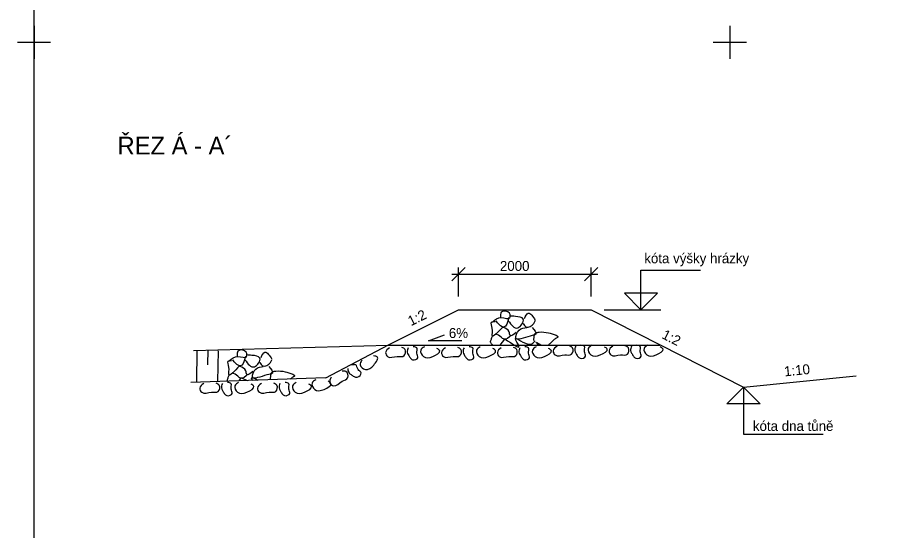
# Model space of a CAD drawing. Extents: x -463095.2 to -463015.6, y -1105044.4 to -1104976.7.
# Drawn here: x -463058.63 to -463032.2, y -1105021.66 to -1105006.18 of the extents above; entities that cross this region are included whole.
import ezdxf

# ---------------------------------------------------------------- set-up
doc = ezdxf.new("R2010")
doc.units = 0
for name, color, linetype in [('Implicitní', 7, 'Continuous'), ('KOTA', 7, 'Continuous'), ('KOTA_DELKY', 7, 'Continuous'), ('NS_V_PF', 7, 'Continuous'), ('REZY_PF_PUVODNI', 7, 'Continuous'), ('SKLON', 7, 'Continuous'), ('Vrstva 14', 7, 'Continuous')]:
    doc.layers.add(name, color=color, linetype=linetype)

msp = doc.modelspace()

# ---------------------------------------------------------------- linework, layer by layer
at = {"layer": 'Implicitní'}
for p, q in [((-463058.132, -1105006.432), (-463058.132, -1105007.432)), ((-463058.132, -1105006.432), (-463058.132, -1105007.432)), ((-463058.132, -1105006.432), (-463058.132, -1105007.432)), ((-463058.132, -1105006.432), (-463058.132, -1105007.432)), ((-463058.132, -1105006.432), (-463058.132, -1105007.432)), ((-463058.132, -1105006.432), (-463058.132, -1105007.432)), ((-463058.132, -1105006.432), (-463058.132, -1105007.432)), ((-463058.132, -1105006.432), (-463058.132, -1105007.432)), ((-463058.132, -1105006.432), (-463058.132, -1105007.432)), ((-463058.132, -1105006.432), (-463058.132, -1105007.432)), ((-463058.132, -1105006.432), (-463058.132, -1105007.432)), ((-463058.132, -1105006.432), (-463058.132, -1105007.432)), ((-463058.132, -1105006.432), (-463058.132, -1105007.432)), ((-463058.132, -1105006.432), (-463058.132, -1105007.432)), ((-463058.132, -1105006.432), (-463058.132, -1105007.432)), ((-463058.132, -1105006.432), (-463058.132, -1105007.432)), ((-463058.132, -1105006.432), (-463058.132, -1105007.432)), ((-463058.132, -1105006.432), (-463058.132, -1105007.432)), ((-463058.132, -1105006.432), (-463058.132, -1105007.432)), ((-463058.132, -1105006.432), (-463058.132, -1105007.432)), ((-463058.132, -1105006.432), (-463058.132, -1105007.432)), ((-463058.132, -1105006.432), (-463058.132, -1105007.432)), ((-463058.132, -1105006.432), (-463058.132, -1105007.432)), ((-463058.132, -1105006.432), (-463058.132, -1105007.432)), ((-463058.132, -1105006.432), (-463058.132, -1105007.432)), ((-463058.132, -1105006.432), (-463058.132, -1105007.432)), ((-463058.132, -1105006.432), (-463058.132, -1105007.432)), ((-463058.132, -1105006.432), (-463058.132, -1105007.432)), ((-463037.132, -1105006.432), (-463037.132, -1105007.432)), ((-463037.132, -1105006.432), (-463037.132, -1105007.432)), ((-463037.132, -1105006.432), (-463037.132, -1105007.432)), ((-463037.132, -1105006.432), (-463037.132, -1105007.432)), ((-463037.132, -1105006.432), (-463037.132, -1105007.432)), ((-463037.132, -1105006.432), (-463037.132, -1105007.432)), ((-463037.132, -1105006.432), (-463037.132, -1105007.432)), ((-463037.132, -1105006.432), (-463037.132, -1105007.432)), ((-463037.132, -1105006.432), (-463037.132, -1105007.432)), ((-463037.132, -1105006.432), (-463037.132, -1105007.432)), ((-463037.132, -1105006.432), (-463037.132, -1105007.432)), ((-463037.132, -1105006.432), (-463037.132, -1105007.432)), ((-463037.132, -1105006.432), (-463037.132, -1105007.432)), ((-463037.132, -1105006.432), (-463037.132, -1105007.432)), ((-463037.132, -1105006.432), (-463037.132, -1105007.432)), ((-463037.132, -1105006.432), (-463037.132, -1105007.432)), ((-463037.132, -1105006.432), (-463037.132, -1105007.432)), ((-463037.132, -1105006.432), (-463037.132, -1105007.432)), ((-463037.132, -1105006.432), (-463037.132, -1105007.432)), ((-463037.132, -1105006.432), (-463037.132, -1105007.432)), ((-463037.132, -1105006.432), (-463037.132, -1105007.432)), ((-463037.132, -1105006.432), (-463037.132, -1105007.432)), ((-463037.132, -1105006.432), (-463037.132, -1105007.432)), ((-463037.132, -1105006.432), (-463037.132, -1105007.432)), ((-463037.132, -1105006.432), (-463037.132, -1105007.432)), ((-463037.132, -1105006.432), (-463037.132, -1105007.432)), ((-463037.132, -1105006.432), (-463037.132, -1105007.432)), ((-463037.132, -1105006.432), (-463037.132, -1105007.432)), ((-463037.132, -1105006.432), (-463037.132, -1105007.432)), ((-463037.132, -1105006.432), (-463037.132, -1105007.432)), ((-463037.132, -1105006.432), (-463037.132, -1105007.432)), ((-463037.132, -1105006.432), (-463037.132, -1105007.432)), ((-463037.132, -1105006.432), (-463037.132, -1105007.432)), ((-463037.132, -1105006.432), (-463037.132, -1105007.432)), ((-463037.132, -1105006.432), (-463037.132, -1105007.432)), ((-463037.132, -1105006.432), (-463037.132, -1105007.432)), ((-463037.132, -1105006.432), (-463037.132, -1105007.432)), ((-463037.132, -1105006.432), (-463037.132, -1105007.432)), ((-463037.132, -1105006.432), (-463037.132, -1105007.432)), ((-463037.132, -1105006.432), (-463037.132, -1105007.432)), ((-463037.132, -1105006.432), (-463037.132, -1105007.432)), ((-463037.132, -1105006.432), (-463037.132, -1105007.432)), ((-463057.632, -1105006.932), (-463058.632, -1105006.932)), ((-463057.632, -1105006.932), (-463058.632, -1105006.932)), ((-463057.632, -1105006.932), (-463058.632, -1105006.932)), ((-463057.632, -1105006.932), (-463058.632, -1105006.932)), ((-463057.632, -1105006.932), (-463058.632, -1105006.932)), ((-463057.632, -1105006.932), (-463058.632, -1105006.932)), ((-463036.632, -1105006.932), (-463037.632, -1105006.932)), ((-463036.632, -1105006.932), (-463037.632, -1105006.932)), ((-463036.632, -1105006.932), (-463037.632, -1105006.932)), ((-463036.632, -1105006.932), (-463037.632, -1105006.932)), ((-463036.632, -1105006.932), (-463037.632, -1105006.932)), ((-463036.632, -1105006.932), (-463037.632, -1105006.932)), ((-463036.632, -1105006.932), (-463037.632, -1105006.932)), ((-463036.632, -1105006.932), (-463037.632, -1105006.932)), ((-463036.632, -1105006.932), (-463037.632, -1105006.932)), ((-463036.632, -1105006.932), (-463037.632, -1105006.932))]:
    msp.add_line(p, q, dxfattribs=at)
msp.add_lwpolyline([(-463058.132, -1104977.232), (-463016.132, -1104977.232), (-463016.132, -1105036.632), (-463058.132, -1105036.632)], close=True, dxfattribs=at)
at = {"layer": 'KOTA'}
for points in [[(-463039.817, -1105014.5), (-463040.317, -1105014.5), (-463039.817, -1105015), (-463039.817, -1105013.8), (-463038.017, -1105013.8)], [(-463039.817, -1105015), (-463039.317, -1105014.5), (-463039.817, -1105014.5)], [(-463043.319, -1105015), (-463041.326, -1105015)], [(-463040.924, -1105015), (-463039.817, -1105015), (-463039.217, -1105015)], [(-463036.723, -1105017.835), (-463037.223, -1105017.835), (-463036.723, -1105017.335), (-463036.723, -1105018.754), (-463034.322, -1105018.754)], [(-463036.723, -1105017.335), (-463036.223, -1105017.835), (-463036.723, -1105017.835)]]:
    msp.add_lwpolyline(points, dxfattribs=at)
at = {"layer": 'KOTA_DELKY'}
for points in [[(-463045.519, -1105014.127), (-463045.119, -1105013.727)], [(-463045.319, -1105014.6), (-463045.319, -1105013.727)], [(-463041.519, -1105014.127), (-463041.119, -1105013.727)], [(-463041.319, -1105014.6), (-463041.319, -1105013.727)], [(-463045.519, -1105013.927), (-463041.119, -1105013.927)]]:
    msp.add_lwpolyline(points, dxfattribs=at)
at = {"layer": 'NS_V_PF'}
for points in [[(-463047.452, -1105016.067), (-463045.319, -1105015), (-463043.319, -1105015), (-463041.319, -1105015), (-463039.238, -1105016.058)], [(-463039.238, -1105016.058), (-463036.723, -1105017.335), (-463033.319, -1105016.994)]]:
    msp.add_lwpolyline(points, dxfattribs=at)
at = {"layer": 'REZY_PF_PUVODNI'}
msp.add_lwpolyline([(-463053.319, -1105016.225), (-463047.443, -1105016.066)], dxfattribs=at)
at = {"layer": 'Vrstva 14'}
for p, q in [((-463047.443, -1105016.066), (-463049.34, -1105017.058)), ((-463047.443, -1105016.066), (-463039.242, -1105016.066)), ((-463043.939, -1105015.881), (-463044.073, -1105016.066)), ((-463042.993, -1105015.979), (-463042.906, -1105016.066)), ((-463042.835, -1105016.066), (-463042.955, -1105015.999)), ((-463053.224, -1105017.189), (-463053.21, -1105016.215)), ((-463052.886, -1105016.659), (-463052.88, -1105016.207)), ((-463052.581, -1105017.167), (-463052.568, -1105016.233)), ((-463049.334, -1105017.054), (-463053.398, -1105017.195)), ((-463051.887, -1105017.056), (-463051.951, -1105017.145)), ((-463051.873, -1105017.05), (-463051.7, -1105017.136)), ((-463050.957, -1105017.111), (-463050.953, -1105017.108))]:
    msp.add_line(p, q, dxfattribs=at)
msp.add_lwpolyline([(-463045.224, -1105015.94), (-463046.227, -1105015.94), (-463045.741, -1105015.752)], dxfattribs=at)
for points in [[(-463044.291, -1105015.365), (-463044.031, -1105015.235), (-463043.771, -1105015.235), (-463043.783, -1105015.105), (-463044.031, -1105015.069), (-463044.055, -1105015.223)], [(-463043.807, -1105015.235), (-463043.961, -1105015.519), (-463044.149, -1105015.389), (-463044.185, -1105015.329)], [(-463043.819, -1105015.329), (-463043.535, -1105015.543), (-463043.371, -1105015.283), (-463043.607, -1105015.199), (-463043.761, -1105015.187)], [(-463043.371, -1105015.413), (-463043.277, -1105015.519), (-463043.053, -1105015.413), (-463043.005, -1105015.329)], [(-463043.335, -1105015.259), (-463043.217, -1105015.105), (-463043.005, -1105015.317)], [(-463043.985, -1105015.519), (-463044.303, -1105015.779), (-463044.303, -1105015.555), (-463044.327, -1105015.377), (-463044.221, -1105015.353)], [(-463043.583, -1105015.685), (-463043.761, -1105015.779), (-463043.795, -1105015.661), (-463043.961, -1105015.531)], [(-463043.099, -1105015.531), (-463042.993, -1105015.733), (-463043.159, -1105015.791), (-463043.595, -1105015.851), (-463043.489, -1105015.613), (-463043.265, -1105015.531)], [(-463044.288, -1105016.066), (-463044.291, -1105016.063), (-463044.305, -1105016.049), (-463044.34, -1105016.006), (-463044.353, -1105015.976), (-463044.354, -1105015.96), (-463044.353, -1105015.953), (-463044.351, -1105015.945), (-463044.337, -1105015.902), (-463044.323, -1105015.86), (-463044.308, -1105015.817), (-463044.293, -1105015.775)], [(-463043.729, -1105015.763), (-463043.949, -1105015.887), (-463044.031, -1105015.827), (-463044.209, -1105015.721)], [(-463043.925, -1105015.875), (-463043.501, -1105016.087), (-463043.607, -1105015.875), (-463043.159, -1105016.039), (-463043.005, -1105015.933)], [(-463043.053, -1105015.921), (-463043.049, -1105015.882), (-463043.044, -1105015.843), (-463043.039, -1105015.804), (-463043.033, -1105015.765), (-463043.031, -1105015.755), (-463043.028, -1105015.745), (-463043.019, -1105015.728), (-463042.988, -1105015.7), (-463042.887, -1105015.671), (-463042.61, -1105015.692), (-463042.373, -1105015.768), (-463042.325, -1105015.809), (-463042.327, -1105015.827), (-463042.337, -1105015.836), (-463042.343, -1105015.839), (-463042.347, -1105015.841), (-463042.349, -1105015.842), (-463042.351, -1105015.843), (-463042.368, -1105015.85), (-463042.417, -1105015.883), (-463042.483, -1105015.942), (-463042.55, -1105016.008), (-463042.584, -1105016.039), (-463042.618, -1105016.066)], [(-463046.841, -1105016.143), (-463046.87, -1105016.278), (-463046.839, -1105016.352), (-463046.784, -1105016.441), (-463046.707, -1105016.508), (-463046.547, -1105016.444), (-463046.579, -1105016.311), (-463046.579, -1105016.15), (-463046.688, -1105016.113)], [(-463046.35, -1105016.113), (-463046.462, -1105016.215), (-463046.383, -1105016.407), (-463046.1, -1105016.407), (-463045.891, -1105016.231), (-463045.975, -1105016.162)], [(-463045.156, -1105016.143), (-463045.185, -1105016.278), (-463045.154, -1105016.352), (-463045.099, -1105016.441), (-463045.022, -1105016.508), (-463044.861, -1105016.444), (-463044.893, -1105016.311), (-463044.893, -1105016.15), (-463045.003, -1105016.113)], [(-463044.664, -1105016.113), (-463044.776, -1105016.215), (-463044.697, -1105016.407), (-463044.415, -1105016.407), (-463044.206, -1105016.231), (-463044.29, -1105016.162)], [(-463043.47, -1105016.143), (-463043.499, -1105016.278), (-463043.469, -1105016.352), (-463043.413, -1105016.441), (-463043.336, -1105016.508), (-463043.176, -1105016.444), (-463043.208, -1105016.311), (-463043.208, -1105016.15), (-463043.317, -1105016.113)], [(-463042.979, -1105016.113), (-463043.091, -1105016.215), (-463043.012, -1105016.407), (-463042.729, -1105016.407), (-463042.52, -1105016.231), (-463042.604, -1105016.162)], [(-463042.348, -1105016.096), (-463042.466, -1105016.239), (-463042.407, -1105016.362), (-463042.117, -1105016.362), (-463041.91, -1105016.336), (-463041.88, -1105016.15), (-463041.976, -1105016.089)], [(-463041.786, -1105016.096), (-463041.814, -1105016.232), (-463041.784, -1105016.306), (-463041.728, -1105016.395), (-463041.651, -1105016.462), (-463041.491, -1105016.398), (-463041.523, -1105016.265), (-463041.523, -1105016.103), (-463041.632, -1105016.067)], [(-463041.294, -1105016.067), (-463041.406, -1105016.169), (-463041.327, -1105016.36), (-463041.044, -1105016.36), (-463040.835, -1105016.184), (-463040.92, -1105016.115)], [(-463040.663, -1105016.096), (-463040.78, -1105016.239), (-463040.722, -1105016.362), (-463040.431, -1105016.362), (-463040.225, -1105016.336), (-463040.194, -1105016.15), (-463040.291, -1105016.089)], [(-463040.1, -1105016.096), (-463040.129, -1105016.232), (-463040.098, -1105016.306), (-463040.043, -1105016.395), (-463039.966, -1105016.462), (-463039.806, -1105016.398), (-463039.838, -1105016.265), (-463039.838, -1105016.103), (-463039.947, -1105016.067)], [(-463039.609, -1105016.067), (-463039.721, -1105016.169), (-463039.642, -1105016.36), (-463039.359, -1105016.36), (-463039.15, -1105016.184), (-463039.234, -1105016.115)], [(-463052.239, -1105016.54), (-463051.979, -1105016.41), (-463051.719, -1105016.41), (-463051.731, -1105016.28), (-463051.979, -1105016.244), (-463052.003, -1105016.398)], [(-463051.767, -1105016.504), (-463051.483, -1105016.718), (-463051.319, -1105016.458), (-463051.555, -1105016.374), (-463051.709, -1105016.362)], [(-463051.283, -1105016.434), (-463051.165, -1105016.28), (-463050.953, -1105016.492)], [(-463047.404, -1105016.143), (-463047.521, -1105016.286), (-463047.463, -1105016.408), (-463047.172, -1105016.408), (-463046.966, -1105016.382), (-463046.935, -1105016.196), (-463047.032, -1105016.135)], [(-463045.719, -1105016.143), (-463045.836, -1105016.286), (-463045.777, -1105016.408), (-463045.487, -1105016.408), (-463045.28, -1105016.382), (-463045.25, -1105016.196), (-463045.347, -1105016.135)], [(-463044.033, -1105016.143), (-463044.15, -1105016.286), (-463044.092, -1105016.408), (-463043.801, -1105016.408), (-463043.595, -1105016.382), (-463043.564, -1105016.196), (-463043.661, -1105016.135)], [(-463051.933, -1105016.694), (-463052.251, -1105016.954), (-463052.251, -1105016.73), (-463052.275, -1105016.552), (-463052.169, -1105016.528)], [(-463051.755, -1105016.41), (-463051.909, -1105016.694), (-463052.097, -1105016.564), (-463052.133, -1105016.504)], [(-463051.319, -1105016.588), (-463051.225, -1105016.694), (-463051.001, -1105016.588), (-463050.953, -1105016.504)], [(-463048.662, -1105016.77), (-463048.626, -1105016.904), (-463048.565, -1105016.956), (-463048.475, -1105017.01), (-463048.376, -1105017.034), (-463048.262, -1105016.904), (-463048.352, -1105016.801), (-463048.425, -1105016.657), (-463048.539, -1105016.674)], [(-463048.238, -1105016.52), (-463048.291, -1105016.662), (-463048.134, -1105016.796), (-463047.882, -1105016.667), (-463047.777, -1105016.415), (-463047.883, -1105016.392)], [(-463051.677, -1105016.938), (-463051.897, -1105017.062), (-463051.979, -1105017.002), (-463052.157, -1105016.896)], [(-463051.531, -1105016.86), (-463051.709, -1105016.954), (-463051.743, -1105016.836), (-463051.909, -1105016.706)], [(-463051.047, -1105016.706), (-463050.941, -1105016.908), (-463051.107, -1105016.966), (-463051.543, -1105017.026), (-463051.437, -1105016.788), (-463051.213, -1105016.706)], [(-463051.001, -1105017.096), (-463050.996, -1105017.057), (-463050.991, -1105017.018), (-463050.986, -1105016.979), (-463050.981, -1105016.94), (-463050.979, -1105016.93), (-463050.976, -1105016.92), (-463050.966, -1105016.903), (-463050.935, -1105016.875), (-463050.835, -1105016.846), (-463050.557, -1105016.867), (-463050.321, -1105016.943), (-463050.272, -1105016.984), (-463050.275, -1105017.002), (-463050.284, -1105017.011), (-463050.291, -1105017.014), (-463050.294, -1105017.016), (-463050.299, -1105017.018), (-463050.305, -1105017.021), (-463050.312, -1105017.024), (-463050.325, -1105017.031), (-463050.351, -1105017.048), (-463050.377, -1105017.068), (-463050.404, -1105017.091)], [(-463049.163, -1105017.027), (-463049.202, -1105017.208), (-463049.094, -1105017.29), (-463048.835, -1105017.157), (-463048.663, -1105017.04), (-463048.721, -1105016.861), (-463048.835, -1105016.851)], [(-463052.298, -1105017.157), (-463052.302, -1105017.139), (-463052.299, -1105017.12), (-463052.285, -1105017.077), (-463052.27, -1105017.035), (-463052.255, -1105016.993), (-463052.241, -1105016.95)], [(-463051.532, -1105017.131), (-463051.542, -1105017.116), (-463051.551, -1105017.101), (-463051.555, -1105017.095), (-463051.558, -1105017.089), (-463051.561, -1105017.083), (-463051.563, -1105017.077), (-463051.565, -1105017.072), (-463051.566, -1105017.068), (-463051.566, -1105017.063), (-463051.566, -1105017.059), (-463051.562, -1105017.053), (-463051.555, -1105017.05), (-463051.529, -1105017.049), (-463051.503, -1105017.054), (-463051.489, -1105017.058), (-463051.474, -1105017.064), (-463051.454, -1105017.074), (-463051.448, -1105017.078), (-463051.412, -1105017.101), (-463051.377, -1105017.125)], [(-463049.63, -1105017.107), (-463049.742, -1105017.209), (-463049.663, -1105017.4), (-463049.38, -1105017.4), (-463049.171, -1105017.224), (-463049.255, -1105017.156)], [(-463053.012, -1105017.221), (-463053.13, -1105017.364), (-463053.071, -1105017.486), (-463052.781, -1105017.486), (-463052.574, -1105017.461), (-463052.544, -1105017.275), (-463052.64, -1105017.214)], [(-463052.45, -1105017.221), (-463052.478, -1105017.356), (-463052.448, -1105017.431), (-463052.393, -1105017.52), (-463052.315, -1105017.587), (-463052.155, -1105017.522), (-463052.187, -1105017.39), (-463052.187, -1105017.228), (-463052.296, -1105017.192)], [(-463051.958, -1105017.192), (-463052.07, -1105017.294), (-463051.991, -1105017.485), (-463051.708, -1105017.485), (-463051.5, -1105017.309), (-463051.584, -1105017.24)], [(-463051.272, -1105017.221), (-463051.39, -1105017.364), (-463051.331, -1105017.486), (-463051.041, -1105017.486), (-463050.834, -1105017.461), (-463050.804, -1105017.275), (-463050.9, -1105017.214)], [(-463050.71, -1105017.221), (-463050.738, -1105017.356), (-463050.708, -1105017.431), (-463050.652, -1105017.52), (-463050.575, -1105017.587), (-463050.415, -1105017.522), (-463050.447, -1105017.39), (-463050.447, -1105017.228), (-463050.556, -1105017.192)], [(-463050.218, -1105017.192), (-463050.33, -1105017.294), (-463050.251, -1105017.485), (-463049.968, -1105017.485), (-463049.76, -1105017.309), (-463049.844, -1105017.24)]]:
    msp.add_spline(points, degree=3, dxfattribs=at)

# ---------------------------------------------------------------- texts
at = {"layer": 'KOTA'}
for s, p in [('kóta výšky hrázky', (-463039.716, -1105013.595)), ('kóta dna tůně', (-463036.438, -1105018.654))]:
    msp.add_text(s, height=0.3, dxfattribs=at).set_placement(p)
at = {"layer": 'KOTA_DELKY'}
for s, p in [('2000', (-463044.073, -1105013.827)), ('6%', (-463045.614, -1105015.85))]:
    msp.add_text(s, height=0.3, dxfattribs=at).set_placement(p)
at = {"layer": 'SKLON'}
for s, rotation, p in [('1:2', 26.5651, (-463046.757, -1105015.496)), ('1:2', 333.0741, (-463039.212, -1105015.846)), ('1:10', 5.7106, (-463035.48, -1105017.01))]:
    msp.add_text(s, height=0.3, rotation=rotation, dxfattribs=at).set_placement(p)
at = {"layer": 'Vrstva 14'}
msp.add_text('ŘEZ Á - A´', height=0.536, dxfattribs=at).set_placement((-463055.613, -1105010.313))

doc.saveas('drawing.dxf')
